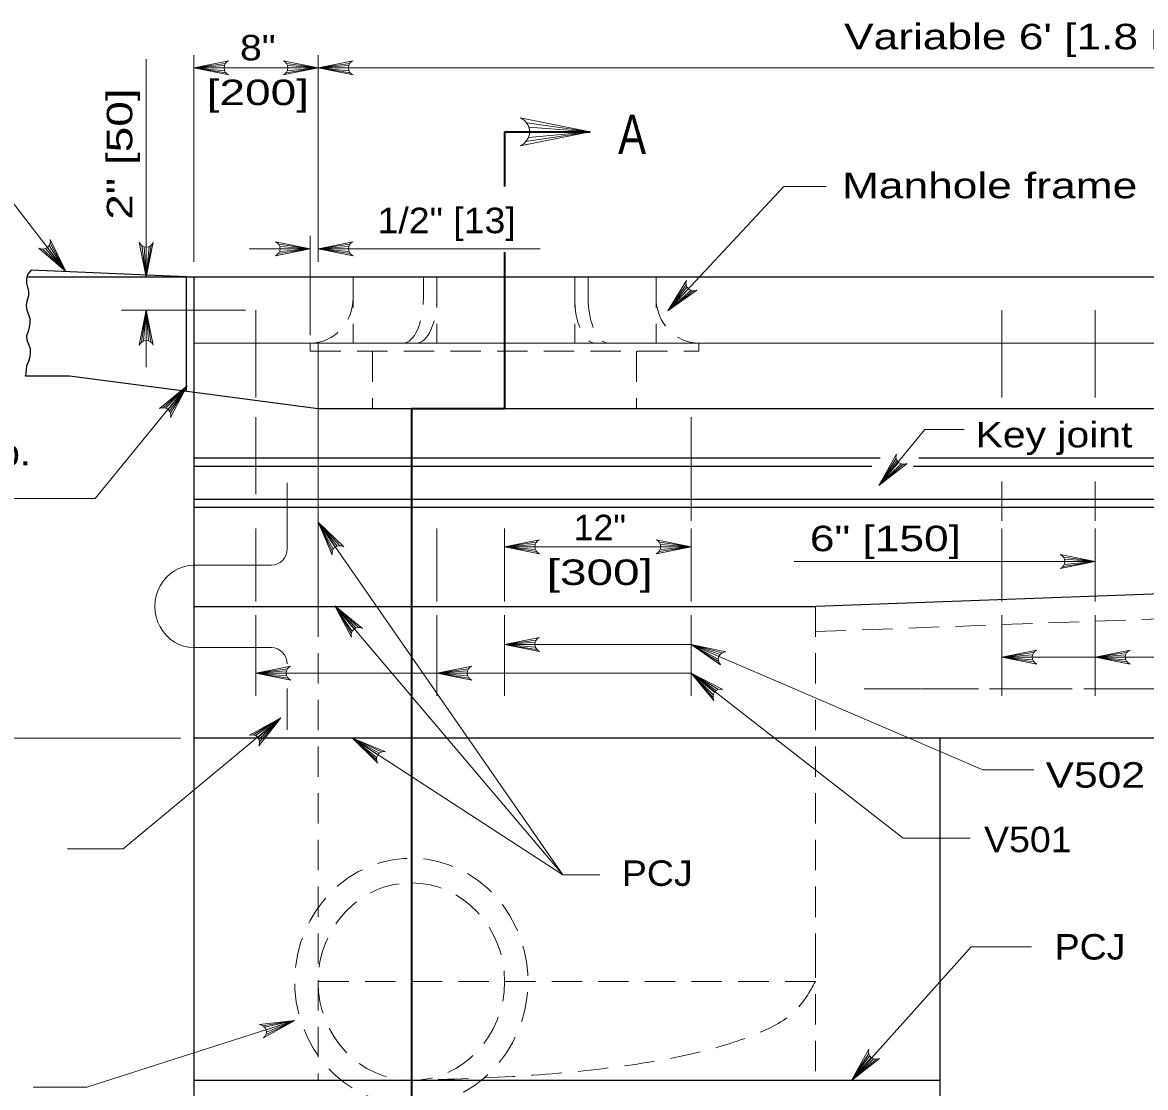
# Model space of a CAD drawing. Extents: x 339.1 to 373.1, y 1412.7 to 1456.7.
# Drawn here: x 344.17 to 351.05, y 1439.06 to 1445.58 of the extents above; entities that cross this region are included whole.
import ezdxf
from ezdxf.enums import TextEntityAlignment as Align

# ---------------------------------------------------------------- set-up
doc = ezdxf.new("R2010")
doc.units = 0
doc.header["$LTSCALE"] = 0.062
doc.linetypes.add('MEDIUM_DASHED', pattern=[4.5, 3, -1.5])
doc.layers.add('1', color=7, linetype='Continuous', lineweight=13)

msp = doc.modelspace()

# ---------------------------------------------------------------- linework, layer by layer
at = {"layer": '1'}
for p, q in [((344.92733, 1444.02142), (344.92733, 1445.35725)), ((345.21833, 1444.11492), (345.21833, 1445.3825)), ((345.97983, 1444.11492), (345.97983, 1445.3825)), ((345.41217, 1445.33092), (345.21825, 1445.30383)), ((345.40558, 1445.3175), (345.21825, 1445.30383)), ((345.75492, 1445.30383), (345.21825, 1445.30383)), ((345.40358, 1445.30383), (345.21825, 1445.30383)), ((345.407, 1445.28642), (345.21825, 1445.30383)), ((345.41442, 1445.27383), (345.21825, 1445.30383)), ((345.97983, 1445.30383), (345.75283, 1445.30383)), ((345.78367, 1445.27383), (345.97983, 1445.30383)), ((345.78592, 1445.33092), (345.97983, 1445.30383)), ((345.79108, 1445.28642), (345.97983, 1445.30383)), ((345.7925, 1445.3175), (345.97983, 1445.30383)), ((345.7945, 1445.30383), (345.97983, 1445.30383)), ((346.17375, 1445.33092), (345.97983, 1445.30383)), ((346.16717, 1445.3175), (345.97983, 1445.30383)), ((346.16517, 1445.30383), (345.97983, 1445.30383)), ((346.16858, 1445.28642), (345.97983, 1445.30383)), ((346.176, 1445.27383), (345.97983, 1445.30383)), ((347.25783, 1444.9665), (347.64558, 1444.91225)), ((347.27092, 1444.93967), (347.64558, 1444.91225)), ((347.25325, 1444.85225), (347.64558, 1444.91225)), ((347.26808, 1444.87742), (347.64558, 1444.91225)), ((347.27492, 1444.91225), (347.64558, 1444.91225)), ((345.93225, 1443.66608), (345.93225, 1444.27475)), ((344.29475, 1444.19392), (344.43375, 1444.056)), ((344.30942, 1444.19683), (344.43375, 1444.056)), ((344.32158, 1444.2035), (344.43375, 1444.056)), ((344.33333, 1444.21683), (344.43375, 1444.056)), ((344.33883, 1444.23033), (344.43375, 1444.056)), ((344.90025, 1444.21533), (344.92733, 1444.02142)), ((344.91367, 1444.20875), (344.92733, 1444.02142)), ((344.95733, 1444.21758), (344.92733, 1444.02142)), ((344.94475, 1444.21017), (344.92733, 1444.02142)), ((344.92733, 1444.20675), (344.92733, 1444.02142)), ((345.55792, 1444.19608), (345.93225, 1444.19608)), ((345.73608, 1444.16608), (345.93225, 1444.19608)), ((345.73833, 1444.22317), (345.93225, 1444.19608)), ((345.7435, 1444.17867), (345.93225, 1444.19608)), ((345.74492, 1444.20975), (345.93225, 1444.19608)), ((345.74692, 1444.19608), (345.93225, 1444.19608)), ((346.17375, 1444.22317), (345.97983, 1444.19608)), ((346.16717, 1444.20975), (345.97983, 1444.19608)), ((345.97983, 1444.19608), (347.34092, 1444.19608)), ((346.16517, 1444.19608), (345.97983, 1444.19608)), ((346.16858, 1444.17867), (345.97983, 1444.19608)), ((346.176, 1444.16608), (345.97983, 1444.19608)), ((346.72808, 1444.02142), (349.57375, 1444.02142)), ((348.234, 1443.97533), (348.12117, 1443.81533)), ((348.23925, 1443.96142), (348.12117, 1443.81533)), ((348.24792, 1443.95058), (348.12117, 1443.81533)), ((348.26292, 1443.94117), (348.12117, 1443.81533)), ((348.27717, 1443.938), (348.12117, 1443.81533)), ((345.53608, 1443.81992), (344.77633, 1443.81992)), ((344.89742, 1443.62367), (344.92733, 1443.81992)), ((344.90992, 1443.63108), (344.92733, 1443.81992)), ((344.92733, 1443.47183), (344.92733, 1443.81992)), ((344.92733, 1443.63458), (344.92733, 1443.81992)), ((344.94108, 1443.63258), (344.92733, 1443.81992)), ((344.9545, 1443.626), (344.92733, 1443.81992)), ((345.59908, 1443.81992), (345.59908, 1443.28475)), ((350.16808, 1443.81992), (350.16808, 1443.28475)), ((350.73917, 1443.81992), (350.73917, 1443.28475)), ((351.37842, 1443.61833), (345.21833, 1443.61833)), ((345.97983, 1443.61833), (345.97983, 1442.00592)), ((345.03042, 1443.22283), (345.17733, 1443.35625)), ((345.04483, 1443.22067), (345.17733, 1443.35625)), ((345.06058, 1443.21242), (345.17733, 1443.35625)), ((345.06992, 1443.20217), (345.17733, 1443.35625)), ((345.07625, 1443.18867), (345.17733, 1443.35625)), ((345.59908, 1443.16433), (345.59908, 1442.69408)), ((348.26433, 1443.16433), (348.26433, 1442.53025)), ((349.52083, 1442.91208), (349.41533, 1442.74725)), ((349.52675, 1442.89842), (349.41533, 1442.74725)), ((349.53592, 1442.888), (349.41533, 1442.74725)), ((349.55133, 1442.87925), (349.41533, 1442.74725)), ((349.56575, 1442.87667), (349.41533, 1442.74725)), ((345.7895, 1442.76167), (345.7895, 1442.3585)), ((350.16808, 1442.77108), (350.16808, 1442.53025)), ((350.73917, 1442.77108), (350.73917, 1442.53025)), ((345.59908, 1442.48217), (345.59908, 1442.03675)), ((346.08525, 1442.36933), (345.97983, 1442.52183)), ((346.07283, 1442.35658), (345.97983, 1442.52183)), ((346.06675, 1442.34333), (345.97983, 1442.52183)), ((346.09767, 1442.3755), (345.97983, 1442.52183)), ((346.11242, 1442.37775), (345.97983, 1442.52183)), ((346.70733, 1442.48217), (346.70733, 1442.03675)), ((347.12208, 1442.48217), (347.12208, 1442.03675)), ((348.26433, 1442.48217), (348.26433, 1442.03675)), ((350.16808, 1442.48217), (350.16808, 1442.03675)), ((350.73917, 1442.48217), (350.73917, 1442.03675)), ((347.316, 1442.39833), (347.12208, 1442.37125)), ((348.0705, 1442.39833), (348.26442, 1442.37125)), ((347.30942, 1442.38492), (347.12208, 1442.37125)), ((347.30742, 1442.37125), (347.12208, 1442.37125)), ((347.31083, 1442.35383), (347.12208, 1442.37125)), ((347.31825, 1442.34125), (347.12208, 1442.37125)), ((348.06825, 1442.34125), (348.26442, 1442.37125)), ((348.07567, 1442.35383), (348.26442, 1442.37125)), ((348.07708, 1442.38492), (348.26442, 1442.37125)), ((348.07908, 1442.37125), (348.26442, 1442.37125)), ((345.21833, 1442.25775), (345.69425, 1442.25775)), ((350.73917, 1442.28075), (348.89542, 1442.28075)), ((350.543, 1442.25075), (350.73917, 1442.28075)), ((350.54525, 1442.30783), (350.73917, 1442.28075)), ((350.55042, 1442.26333), (350.73917, 1442.28075)), ((350.55183, 1442.29442), (350.73917, 1442.28075)), ((350.55383, 1442.28075), (350.73917, 1442.28075)), ((346.20008, 1441.86658), (346.08267, 1442.01)), ((346.18883, 1441.85292), (346.08267, 1442.01)), ((346.18375, 1441.83925), (346.08267, 1442.01)), ((346.212, 1441.87375), (346.08267, 1442.01)), ((346.2265, 1441.87717), (346.08267, 1442.01)), ((347.479, 1440.362), (346.08267, 1442.01)), ((345.59908, 1441.95242), (345.59908, 1441.45883)), ((346.70733, 1441.95242), (346.70733, 1441.45883)), ((347.12208, 1441.95242), (347.12208, 1441.45883)), ((348.26433, 1441.95242), (348.26433, 1441.45883)), ((350.16808, 1441.95242), (350.16808, 1441.45883)), ((350.73917, 1441.95242), (350.73917, 1441.45883)), ((347.316, 1441.80008), (347.12208, 1441.77292)), ((347.30942, 1441.78667), (347.12208, 1441.77292)), ((348.26433, 1441.77292), (347.12208, 1441.77292)), ((347.30742, 1441.77292), (347.12208, 1441.77292)), ((347.31083, 1441.7555), (347.12208, 1441.77292)), ((347.31825, 1441.74292), (347.12208, 1441.77292)), ((348.43458, 1441.69983), (348.26433, 1441.77292)), ((348.43092, 1441.6825), (348.26433, 1441.77292)), ((348.43275, 1441.668), (348.26433, 1441.77292)), ((348.44183, 1441.71158), (348.26433, 1441.77292)), ((348.45317, 1441.72133), (348.26433, 1441.77292)), ((348.26433, 1441.77292), (350.05133, 1441.00575)), ((345.21833, 1441.75408), (345.69425, 1441.75408)), ((350.36192, 1441.72317), (350.16808, 1441.696)), ((350.35542, 1441.70975), (350.16808, 1441.696)), ((350.93308, 1441.72317), (350.73917, 1441.696)), ((350.9265, 1441.70975), (350.73917, 1441.696)), ((350.35342, 1441.696), (350.16808, 1441.696)), ((350.35683, 1441.67858), (350.16808, 1441.696)), ((350.36425, 1441.66608), (350.16808, 1441.696)), ((350.9245, 1441.696), (350.73917, 1441.696)), ((350.92792, 1441.67858), (350.73917, 1441.696)), ((350.93533, 1441.66608), (350.73917, 1441.696)), ((345.793, 1441.62433), (345.59908, 1441.59717)), ((345.78642, 1441.61092), (345.59908, 1441.59717)), ((345.78442, 1441.59717), (345.59908, 1441.59717)), ((345.78783, 1441.57975), (345.59908, 1441.59717)), ((345.79525, 1441.56717), (345.59908, 1441.59717)), ((346.90125, 1441.62433), (346.70733, 1441.59717)), ((346.89467, 1441.61092), (346.70733, 1441.59717)), ((346.89267, 1441.59717), (346.70733, 1441.59717)), ((346.89608, 1441.57975), (346.70733, 1441.59717)), ((346.9035, 1441.56717), (346.70733, 1441.59717)), ((348.40892, 1441.481), (348.2645, 1441.59717)), ((348.40067, 1441.46533), (348.2645, 1441.59717)), ((348.39858, 1441.45083), (348.2645, 1441.59717)), ((348.41908, 1441.49042), (348.2645, 1441.59717)), ((348.43258, 1441.49683), (348.2645, 1441.59717)), ((345.7895, 1441.50325), (345.7895, 1441.25025)), ((349.67658, 1441.50208), (349.32533, 1441.50208)), ((350.02558, 1441.50208), (349.67917, 1441.50208)), ((350.598, 1441.50208), (350.09292, 1441.50208)), ((351.17533, 1441.50208), (350.67025, 1441.50208)), ((345.58267, 1441.21925), (345.75208, 1441.32267)), ((345.59642, 1441.21442), (345.75208, 1441.32267)), ((345.61025, 1441.20325), (345.75208, 1441.32267)), ((345.61758, 1441.1915), (345.75208, 1441.32267)), ((345.62117, 1441.177), (345.75208, 1441.32267)), ((345.13775, 1441.19975), (342.42408, 1441.19975)), ((346.34525, 1441.09658), (346.19125, 1441.19975)), ((346.33842, 1441.08025), (346.19125, 1441.19975)), ((346.33758, 1441.06567), (346.19125, 1441.19975)), ((346.3545, 1441.10692), (346.19125, 1441.19975)), ((346.36742, 1441.11442), (346.19125, 1441.19975)), ((347.479, 1440.362), (346.19125, 1441.19975)), ((350.05133, 1441.00575), (350.36367, 1441.00575)), ((349.98075, 1439.92058), (349.24625, 1439.10358)), ((349.98075, 1439.92058), (350.34933, 1439.92058)), ((345.64125, 1439.4385), (345.83717, 1439.46983)), ((345.65217, 1439.42883), (345.83717, 1439.46983)), ((345.66075, 1439.41333), (345.83717, 1439.46983)), ((345.66083, 1439.38483), (345.83717, 1439.46983)), ((345.663, 1439.39967), (345.83717, 1439.46983)), ((349.3525, 1439.26808), (349.24625, 1439.10358)), ((349.35833, 1439.25433), (349.24625, 1439.10358)), ((349.36742, 1439.24383), (349.24625, 1439.10358)), ((349.38283, 1439.235), (349.24625, 1439.10358)), ((349.39725, 1439.23242), (349.24625, 1439.10358))]:
    msp.add_line(p, q, dxfattribs=at)
at = {"layer": '1', "lineweight": 35}
for p, q in [((347.12208, 1444.91225), (347.64558, 1444.91225)), ((347.12208, 1444.91225), (347.12208, 1444.57767)), ((347.12208, 1444.17467), (347.12208, 1444.13)), ((347.12208, 1444.13), (347.12208, 1443.21525)), ((347.12208, 1443.21525), (346.551, 1443.21525)), ((346.551, 1443.21525), (346.551, 1442.20125)), ((346.551, 1439.64317), (346.551, 1437.88075))]:
    msp.add_line(p, q, dxfattribs=at)
at = {"layer": '1', "lineweight": 25}
for p, q in [((345.21833, 1444.02142), (344.22167, 1444.06533)), ((360.4375, 1444.02142), (345.16325, 1444.02142)), ((345.17092, 1444.02142), (345.17092, 1443.32233)), ((345.21833, 1444.02142), (345.21833, 1441.19975)), ((344.45683, 1443.41675), (344.1875, 1443.41675)), ((346.551, 1443.21525), (345.97983, 1443.21525)), ((357.30708, 1443.21525), (347.12208, 1443.21525)), ((349.42283, 1442.91292), (345.21833, 1442.91292)), ((358.06858, 1442.91292), (349.66017, 1442.91292)), ((349.37233, 1442.8625), (345.21833, 1442.8625)), ((358.06858, 1442.8625), (349.62733, 1442.8625)), ((351.31033, 1442.61058), (345.21833, 1442.61058)), ((348.97067, 1442.00592), (357.30708, 1442.30825)), ((345.21833, 1442.00592), (349.02583, 1442.00592)), ((345.21833, 1441.19975), (345.21833, 1438.29742)), ((349.78733, 1439.10358), (345.21833, 1439.10358))]:
    msp.add_line(p, q, dxfattribs=at)
at = {"layer": '1', "linetype": 'MEDIUM_DASHED'}
for p, q in [((346.194, 1444.02142), (346.194, 1443.61833)), ((346.62492, 1444.02142), (346.62492, 1443.89542)), ((346.70733, 1444.02142), (346.70733, 1443.61833)), ((347.55183, 1444.02142), (347.55183, 1443.61833)), ((347.63425, 1444.02142), (347.63425, 1443.89542)), ((348.05017, 1444.02142), (348.05017, 1443.61833)), ((345.93225, 1443.56792), (345.93225, 1443.61833)), ((345.93225, 1443.56792), (348.31192, 1443.56792)), ((346.313, 1443.56792), (346.313, 1443.21525)), ((347.93117, 1443.56792), (347.93117, 1443.21525)), ((348.31192, 1443.56792), (348.31192, 1443.61833)), ((345.97983, 1442.00592), (345.97983, 1439.10358)), ((349.02583, 1442.00592), (349.02583, 1439.91758)), ((349.02583, 1439.91758), (349.02583, 1439.10358)), ((347.59792, 1439.70825), (345.97983, 1439.70825)), ((349.02583, 1439.70825), (347.59792, 1439.70825))]:
    msp.add_line(p, q, dxfattribs=at)
at = {"layer": '1'}
for points in [[(345.43242, 1445.261), (345.21825, 1445.30383), (345.43242, 1445.34667)], [(345.76567, 1445.261), (345.97983, 1445.30383), (345.76567, 1445.34667)], [(346.194, 1445.261), (345.97983, 1445.30383), (346.194, 1445.34667)], [(357.30708, 1445.30383), (354.73217, 1445.30383), (345.97983, 1445.30383)], [(344.43375, 1444.056), (343.529, 1445.23283), (343.23208, 1445.23283)], [(347.21725, 1444.82658), (347.64558, 1444.91225), (347.21725, 1444.99792)], [(348.12117, 1443.81533), (348.83183, 1444.57692), (349.09167, 1444.57692)], [(344.33825, 1444.25242), (344.43375, 1444.056), (344.27, 1444.20058)], [(344.97017, 1444.23558), (344.92733, 1444.02142), (344.8845, 1444.23558)], [(345.71808, 1444.15325), (345.93225, 1444.19608), (345.71808, 1444.23892)], [(346.194, 1444.15325), (345.97983, 1444.19608), (346.194, 1444.23892)], [(348.29883, 1443.94233), (348.12117, 1443.81533), (348.23633, 1444.00092)], [(344.8845, 1443.60575), (344.92733, 1443.81992), (344.97017, 1443.60575)], [(345.17733, 1443.35625), (344.61408, 1442.66708), (343.97542, 1442.66708)], [(345.00908, 1443.217), (345.17733, 1443.35625), (345.07558, 1443.163)], [(349.41533, 1442.74725), (349.69592, 1443.09), (349.93633, 1443.09)], [(349.58717, 1442.882), (349.41533, 1442.74725), (349.52217, 1442.93775)], [(346.06642, 1442.32125), (345.97983, 1442.52183), (346.13683, 1442.37)], [(345.97983, 1442.52183), (347.479, 1440.362), (347.70642, 1440.362)], [(347.33625, 1442.32842), (347.12208, 1442.37125), (347.33625, 1442.41408)], [(348.05025, 1442.32842), (348.26442, 1442.37125), (348.05025, 1442.41408)], [(347.12208, 1442.37125), (347.89442, 1442.37125), (348.26442, 1442.37125)], [(350.525, 1442.23792), (350.73917, 1442.28075), (350.525, 1442.32358)], [(346.18525, 1441.81717), (346.08267, 1442.01), (346.2515, 1441.87142)], [(347.33625, 1441.73008), (347.12208, 1441.77292), (347.33625, 1441.81575)], [(348.44425, 1441.64908), (348.26433, 1441.77292), (348.478, 1441.72783)], [(350.38225, 1441.65317), (350.16808, 1441.696), (350.38225, 1441.73883)], [(350.95333, 1441.65317), (350.73917, 1441.696), (350.95333, 1441.73883)], [(345.81325, 1441.55433), (345.59908, 1441.59717), (345.81325, 1441.64)], [(346.9215, 1441.55433), (346.70733, 1441.59717), (346.9215, 1441.64)], [(350.16808, 1441.696), (350.73917, 1441.696), (351.31033, 1441.696), (351.88142, 1441.696), (352.4525, 1441.696), (353.02367, 1441.696), (353.59475, 1441.696), (354.16592, 1441.696)], [(345.59908, 1441.59717), (346.70733, 1441.59717), (348.2645, 1441.59717)], [(348.40458, 1441.42958), (348.2645, 1441.59717), (348.45825, 1441.49633)], [(348.2645, 1441.59717), (349.56392, 1440.58725), (349.97458, 1440.58725)], [(345.75208, 1441.32267), (344.78625, 1440.52058), (344.44508, 1440.52058)], [(345.56058, 1441.2175), (345.75208, 1441.32267), (345.61583, 1441.15192)], [(346.34542, 1441.045), (346.19125, 1441.19975), (346.393, 1441.11617)], [(345.83717, 1439.46983), (344.56258, 1439.06125), (344.23408, 1439.06125)], [(345.62017, 1439.44525), (345.83717, 1439.46983), (345.64633, 1439.36367)], [(349.41867, 1439.23767), (349.24625, 1439.10358), (349.35392, 1439.29367)]]:
    msp.add_lwpolyline(points, dxfattribs=at)
at = {"layer": '1', "lineweight": 25}
for points in [[(344.22167, 1444.06533), (344.20033, 1444.03783), (344.19308, 1444.01208), (344.19358, 1443.98533), (344.19908, 1443.96008), (344.2055, 1443.93333), (344.20508, 1443.90533), (344.19483, 1443.8745), (344.19142, 1443.84833), (344.19567, 1443.82025), (344.20508, 1443.794), (344.214, 1443.76817), (344.2145, 1443.74058), (344.20975, 1443.71525), (344.20292, 1443.6895), (344.19392, 1443.66183), (344.1965, 1443.6365), (344.20633, 1443.61117), (344.21575, 1443.58592), (344.21708, 1443.55958), (344.2145, 1443.53425), (344.2055, 1443.50575), (344.19358, 1443.47942), (344.19183, 1443.45417), (344.1875, 1443.41675), (344.18842, 1443.42075)], [(345.21833, 1444.02142), (344.27925, 1444.02142), (344.19525, 1444.02142)], [(345.97983, 1443.21525), (345.19125, 1443.31958), (344.45683, 1443.41675)], [(358.06858, 1442.661), (351.29075, 1442.661), (345.21833, 1442.661)], [(349.78733, 1441.19975), (349.78733, 1438.29742), (345.21833, 1438.29742)], [(358.06858, 1441.19975), (345.50033, 1441.19975), (345.21833, 1441.19975)]]:
    msp.add_lwpolyline(points, dxfattribs=at)
at = {"layer": '1', "linetype": 'MEDIUM_DASHED'}
msp.add_lwpolyline([(349.02583, 1441.85192), (356.73592, 1442.13683), (357.30708, 1442.30825)], dxfattribs=at)
at = {"layer": '1', "lineweight": 35}
msp.add_lwpolyline([(346.551, 1442.20125), (346.551, 1440.62883), (346.551, 1439.64317)], dxfattribs=at)
at = {"layer": '1'}
for centre, radius, start, end in [((345.44972, 1445.30385), 0.04623, 112.08782, 247.91395), ((345.74838, 1445.30385), 0.04623, 292.08605, 67.91218), ((346.21131, 1445.30385), 0.04623, 112.08782, 247.91395), ((347.18268, 1444.91235), 0.09245, 292.08605, 67.91218), ((344.29361, 1444.24023), 0.04623, 239.33013, 15.15626), ((344.92732, 1444.25289), 0.04623, 202.08782, 337.91395), ((345.70078, 1444.19612), 0.04623, 292.08605, 67.91218), ((346.21131, 1444.19612), 0.04623, 112.08782, 247.91395), ((348.27941, 1443.98426), 0.04623, 158.94493, 294.77106), ((344.92741, 1443.58841), 0.04623, 22.08782, 157.91395), ((345.03151, 1443.17654), 0.04623, 343.01335, 118.83948), ((349.56587, 1442.92304), 0.04623, 161.50199, 297.32812), ((347.35355, 1442.37128), 0.04623, 112.08782, 247.91395), ((348.03295, 1442.37128), 0.04623, 292.08605, 67.91218), ((346.1115, 1442.33142), 0.04623, 56.74411, 192.57024), ((350.50771, 1442.28078), 0.04623, 292.08605, 67.91218), ((346.22938, 1441.83094), 0.04623, 61.39666, 197.22279), ((347.35355, 1441.77298), 0.04623, 112.08782, 247.91395), ((348.47703, 1441.68166), 0.04623, 88.85316, 224.67928), ((350.39952, 1441.69609), 0.04623, 112.08782, 247.91395), ((350.97064, 1441.69609), 0.04623, 112.08782, 247.91395), ((345.83056, 1441.59723), 0.04623, 112.08782, 247.91395), ((346.93882, 1441.59723), 0.04623, 112.08782, 247.91395), ((348.44491, 1441.45215), 0.04623, 73.27946, 209.10559), ((345.57501, 1441.17353), 0.04623, 332.17997, 108.0061), ((346.38361, 1441.07098), 0.04623, 78.28182, 214.10795), ((345.6168, 1439.39917), 0.04623, 309.86194, 85.68807), ((349.39756, 1439.27877), 0.04623, 161.26151, 297.08764)]:
    msp.add_arc(centre, radius, start, end, dxfattribs=at)
at = {"layer": '1', "linetype": 'MEDIUM_DASHED'}
for centre, major_axis, ratio, start_param, end_param in [((345.93225, 1443.89546), (0, -0.27713), 0.944544, 0, 1.5707963), ((346.49969, 1443.89546), (0, -0.27713), 0.451773, 6.2831853, 7.8539816), ((346.58212, 1443.89546), (0, -0.27713), 0.451773, 6.2831853, 7.8539816), ((347.67699, 1443.89546), (0, -0.27713), 0.451772, 4.712389, 6.2831853), ((347.75942, 1443.89546), (0, -0.27713), 0.451772, 4.712389, 6.2831853), ((348.31192, 1443.89546), (0, -0.27713), 0.944544, 4.7123891, 6.2831854), ((346.55096, 1439.70825), (0, 0.75581), 0.944544, 3.4075289, 9.6907142)]:
    msp.add_ellipse(centre, major_axis=major_axis, ratio=ratio, start_param=start_param, end_param=end_param, dxfattribs=at)
at = {"layer": '1'}
for centre, major_axis, start_param, end_param in [((345.69428, 1442.35853), (0, -0.10078), 0, 1.5707963), ((345.21835, 1442.00592), (0, 0.25194), 6.2831853, 9.424778), ((345.69428, 1441.65331), (0, 0.10078), 4.712389, 6.2831853)]:
    msp.add_ellipse(centre, major_axis=major_axis, ratio=0.944544, start_param=start_param, end_param=end_param, dxfattribs=at)
at = {"layer": '1', "linetype": 'MEDIUM_DASHED'}
msp.add_ellipse((346.55096, 1439.70825), major_axis=(0, 0.60465), ratio=0.944544, dxfattribs=at)
msp.add_spline([(349.02583, 1439.70825), (348.908, 1439.5355), (348.67217, 1439.3915), (348.33475, 1439.28158), (347.87642, 1439.19533), (347.25817, 1439.13242), (346.551, 1439.10358)], degree=3, dxfattribs=at)

# ---------------------------------------------------------------- texts
at = {"layer": '1'}
for s, height, width, p in [("Variable 6' [1.8 m] to 20' [6.0 m]", 0.156, 1.3, (349.20175, 1445.41742)), ('A', 0.24, 0.8, (347.81775, 1444.77667)), ('Manhole frame', 0.156, 1.3, (349.18883, 1444.50517)), ('Key joint', 0.156, 1.2, (350.00742, 1442.97983)), ('1/2" [13] exp.', 0.156, 1.15, (342.81417, 1442.86958)), ('V502', 0.156, 1.25, (350.43592, 1440.896)), ('V501', 0.156, 1.1, (350.05933, 1440.50092)), ('PCJ', 0.156, 1.1, (347.84067, 1440.29433)), ('PCJ', 0.156, 1.1, (350.4915, 1439.84333))]:
    msp.add_text(s, height=height, dxfattribs=dict(at, width=width)).set_placement(p)
for s, width, p in [('8"', 1.15, (345.61071, 1445.34967)), ('[200]', 1.35, (345.61079, 1445.07567)), ('1/2" [13]', 1.1, (346.76733, 1444.29133)), ('12"', 1.05, (347.70521, 1442.41117)), ('6" [150]', 1.3, (349.45487, 1442.344)), ('[300]', 1.4, (347.70529, 1442.13717))]:
    msp.add_text(s, height=0.156, dxfattribs=dict(at, width=width)).set_placement(p, align=Align.CENTER)
at = {"layer": '1', "width": 1.35}
msp.add_text('2" [50]', height=0.156, rotation=90, dxfattribs=at).set_placement((344.84167, 1444.3735))

doc.saveas('drawing.dxf')
